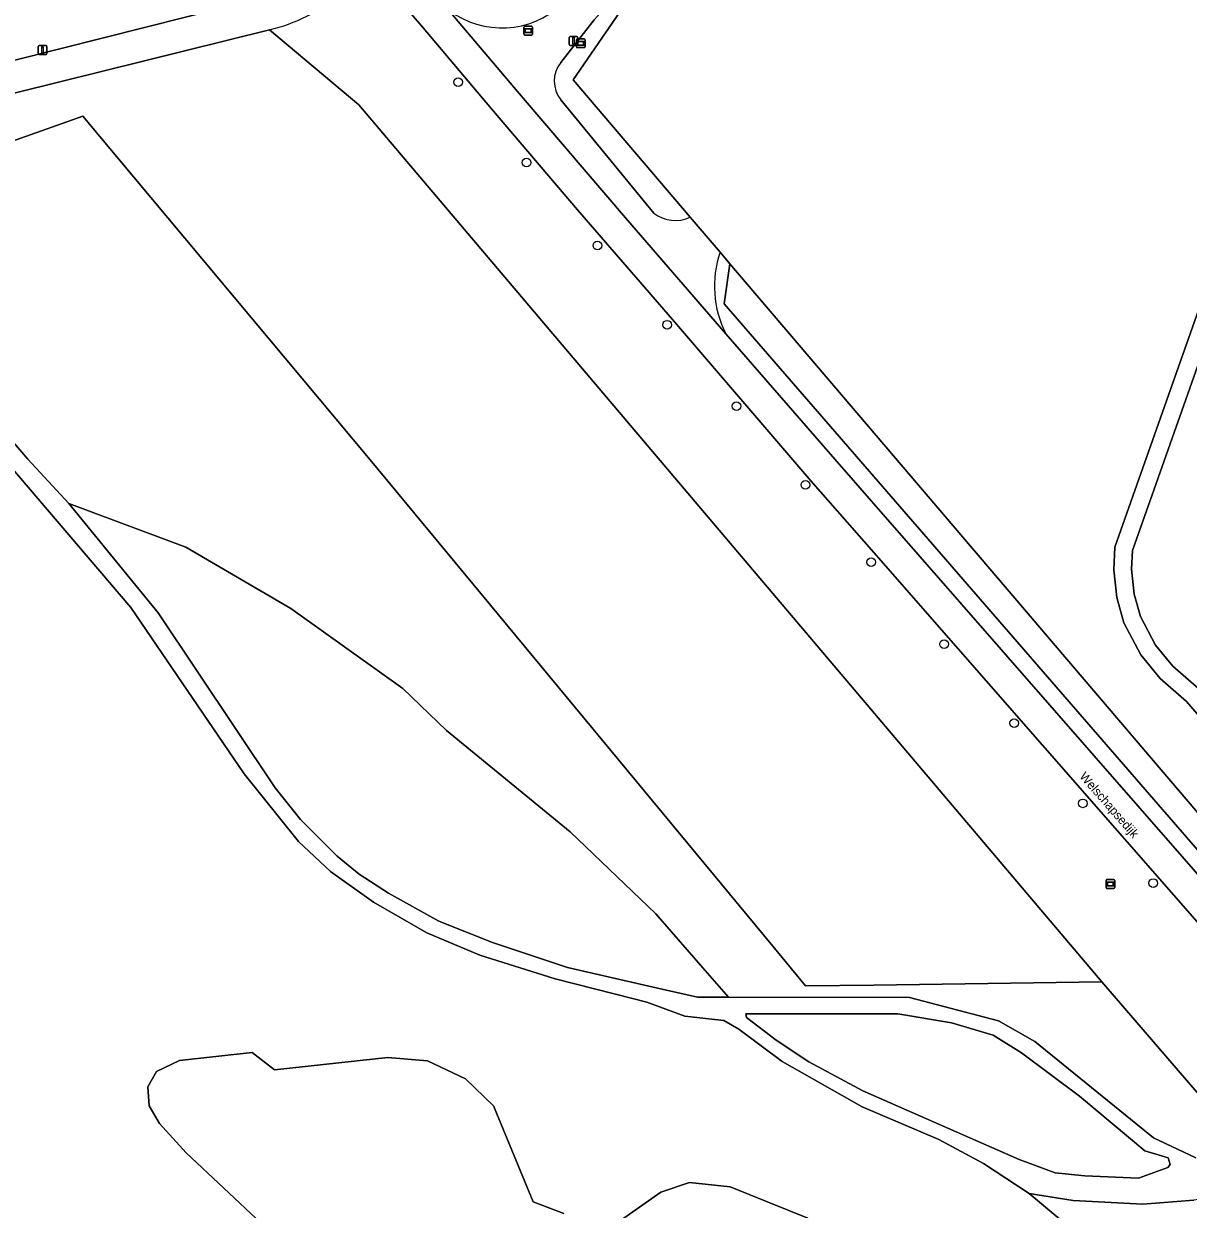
# Model space of a CAD drawing. Extents: x 156061 to 157804, y 383437 to 385640.
# Drawn here: x 156904 to 157035.5, y 384500.7 to 384634.6 of the extents above; entities that cross this region are included whole.
import ezdxf

# ---------------------------------------------------------------- set-up
doc = ezdxf.new("R2010")
doc.units = 0
for name, color, linetype in [('IMGEO_Afsluitpaal', 7, 'Continuous'), ('IMGEO_Berm_groen', 7, 'Continuous'), ('IMGEO_Boom', 7, 'Continuous'), ('IMGEO_Fietspad_gesloten', 7, 'Continuous'), ('IMGEO_Grasland_overig', 7, 'Continuous'), ('IMGEO_Groenvoorziening', 7, 'Continuous'), ('IMGEO_Hek', 7, 'Continuous'), ('IMGEO_Informatiebord', 7, 'Continuous'), ('IMGEO_Lichtmast', 7, 'Continuous'), ('IMGEO_Loofbos', 7, 'Continuous'), ('IMGEO_Openbare_ruimte_label', 7, 'Continuous'), ('IMGEO_Verklikker', 7, 'Continuous')]:
    doc.layers.add(name, color=color, linetype=linetype)

msp = doc.modelspace()

# ---------------------------------------------------------------- linework, layer by layer
at = {"layer": 'IMGEO_Afsluitpaal'}
for p, q in [((156965.58, 384632.24), (156965.58, 384633.04)), ((156965.58, 384633.04), (156965.58, 384632.24)), ((156965.68, 384633.14), (156966.47, 384633.14)), ((156966.47, 384633.14), (156965.68, 384633.14)), ((156966.47, 384632.14), (156965.68, 384632.14)), ((156965.68, 384632.14), (156966.47, 384632.14)), ((156966.57, 384633.04), (156966.57, 384632.24)), ((156966.57, 384632.24), (156966.57, 384633.04))]:
    msp.add_line(p, q, dxfattribs=at)
msp.add_lwpolyline([(156966, 384633.02), (156966.15, 384633.02), (156966.15, 384632.27), (156966, 384632.27), (156966, 384633.02)], dxfattribs=at)
for centre, start, end in [((156965.68, 384633.04), 90, 180), ((156965.68, 384633.04), 90, 180), ((156965.68, 384632.24), 180, 270), ((156965.68, 384632.24), 180, 270), ((156966.47, 384633.04), 0, 90), ((156966.47, 384633.04), 360, 90), ((156966.47, 384632.24), 270, 0), ((156966.47, 384632.24), 270, 0)]:
    msp.add_arc(centre, 0.1, start, end, dxfattribs=at)
at = {"layer": 'IMGEO_Berm_groen'}
for points in [[(157000, 384574.89), (156992.9, 384582.99), (156977.24, 384601.18), (156966.54, 384613.57), (156956.8, 384625), (156948.92, 384634.34), (156945.58, 384638.24)], [(156931.72, 384633.9), (156941.82, 384625.42), (157025.77, 384526.43), (157043.96, 384505.31), (157056.89, 384509.94), (157000, 384574.89)], [(157000, 384583.48), (156983.08, 384602.98), (156983.75, 384607.5), (156982.63, 384608.81)], [(156983.28, 384599.59), (156995.58, 384585.44), (157000, 384580.39), (157044.99, 384528.95)], [(157047.94, 384528.23), (157046.85, 384529.47), (157000, 384583.48)]]:
    msp.add_lwpolyline(points, dxfattribs=at)
for centre, radius, start, end in [((156927.2, 384652.9), 19.53, 283.3871, 309.9373), ((156957.98, 384644.09), 9.97, 233.2442, 312.8511), ((156994.02, 384604.98), 12.02, 161.4536, 206.6743)]:
    msp.add_arc(centre, radius, start, end, dxfattribs=at)
at = {"layer": 'IMGEO_Boom'}
for centre in [(156953.04, 384628), (156960.78, 384618.93), (156968.77, 384609.56), (156976.65, 384600.61), (156984.48, 384591.41), (156992.27, 384582.53), (156999.7, 384573.79), (157007.93, 384564.55), (157015.85, 384555.62), (157023.62, 384546.57), (157031.55, 384537.57)]:
    msp.add_circle(centre, 0.489, dxfattribs=at)
at = {"layer": 'IMGEO_Fietspad_gesloten'}
for points in [[(156934.94, 384639.2), (156931.97, 384637.82), (156888.89, 384626.92), (156886.5, 384626.31), (156885.81, 384626.14)], [(156945.58, 384638.24), (156948.92, 384634.34), (156956.8, 384625), (156966.54, 384613.57), (156977.24, 384601.18), (156992.9, 384582.99), (157000, 384574.89), (157056.89, 384509.94), (157058.63, 384507.87), (157065.54, 384500), (157136.46, 384419.32), (157161.96, 384390.33), (157163.6, 384388.4), (157250.85, 384289.34), (157285.45, 384250), (157313.49, 384218.11)], [(157139.19, 384421.58), (157070.34, 384500), (157064.75, 384506.36), (157062.1, 384509.4), (157060.34, 384511.41), (157052.37, 384520.52), (157044.99, 384528.95), (157000, 384580.39), (156995.58, 384585.44), (156983.28, 384599.59), (156971.95, 384612.68), (156960.39, 384626.17), (156952.01, 384636.1)], [(156886.51, 384622.67), (156886.95, 384622.78), (156888.9, 384623.27), (156931.72, 384633.9)]]:
    msp.add_lwpolyline(points, dxfattribs=at)
msp.add_arc((156927.2, 384652.9), 19.53, 283.3871, 309.9373, dxfattribs=at)
at = {"layer": 'IMGEO_Grasland_overig'}
for points in [[(156964.63, 384630.23), (156968.41, 384635.04), (156970.77, 384637.72), (156972.78, 384640.58), (156980.96, 384652.91), (156993.25, 384670.61)], [(156952.01, 384636.1), (156960.39, 384626.17), (156971.95, 384612.68), (156983.28, 384599.59)], [(156975.15, 384613.22), (156964.64, 384625.99)], [(157040.94, 384614.31), (157027.24, 384575.5), (157027.1, 384572.94), (157027.45, 384569.81), (157028.23, 384566.94), (157030.15, 384563.32), (157032.33, 384560.65), (157035.31, 384558.06), (157042.95, 384549.21)], [(157036.73, 384559.48), (157033.77, 384562.04), (157031.82, 384564.43), (157030.11, 384567.68), (157029.42, 384570.18), (157029.11, 384573), (157029.23, 384575.1), (157042.84, 384613.69)], [(156982.63, 384608.81), (156979.27, 384612.75)], [(157036.38, 384506.54), (157031.6, 384508.79), (157018.2, 384519.68), (157014.07, 384522.01), (157004.02, 384524.63), (156983.59, 384524.68), (156980.07, 384524.69), (156975.43, 384525.74), (156965.39, 384528.02), (156956.92, 384530.86), (156950.86, 384533.28), (156945.16, 384536.42), (156941.85, 384538.59), (156939.37, 384540.6), (156935.23, 384544.74), (156932.38, 384548.32), (156919.14, 384568.06), (156909.06, 384580.42), (156904.43, 384585.42), (156896.64, 384594.46)], [(156900.93, 384586.38), (156916.07, 384568.69), (156928.86, 384549.9), (156935, 384542.26), (156938.61, 384538.86), (156943.48, 384535.42), (156949.52, 384531.94), (156955.48, 384529.42), (156964.01, 384526.75), (156972.89, 384524.49), (156974.36, 384524.11), (156978.64, 384522.54), (156983.06, 384522.07), (156984.77, 384521.07), (156989.64, 384517.42), (156998.67, 384512.3), (157007.35, 384508.6), (157012.39, 384505.9), (157017.56, 384502.51), (157022.53, 384501.72), (157030.4, 384501.33), (157036.14, 384501.76)]]:
    msp.add_lwpolyline(points, dxfattribs=at)
msp.add_lwpolyline([(156985.54, 384522.81), (157002.71, 384522.81), (157008.76, 384521.77), (157013.5, 384520.38), (157016.7, 384518.42), (157023.25, 384513.52), (157030.63, 384507.32), (157033.25, 384506.55), (157033.47, 384505.8), (157033.22, 384505.45), (157029.91, 384504.26), (157023.82, 384504.52), (157020.48, 384504.87), (157016.4, 384506.34), (156998.77, 384514.12), (156992.67, 384517.4), (156988.97, 384519.83), (156985.6, 384522.4)], close=True, dxfattribs=at)
for centre, radius, start, end in [((156957.98, 384644.09), 9.97, 233.2442, 312.8511), ((156967.29, 384628.11), 3.39, 141.4401, 218.776), ((156977.6, 384616.38), 4, 232.2364, 294.7106), ((156994.02, 384604.98), 12.02, 161.4536, 206.6743)]:
    msp.add_arc(centre, radius, start, end, dxfattribs=at)
at = {"layer": 'IMGEO_Groenvoorziening'}
for points in [[(156966.05, 384628.27), (157109.09, 384836.1)], [(157109.09, 384836.1), (156966.05, 384628.27), (156979.27, 384612.75), (156982.63, 384608.81), (156983.75, 384607.5), (157050.93, 384528.66), (157054.27, 384530.42), (157042.95, 384549.21), (157035.31, 384558.06), (157032.33, 384560.65), (157030.15, 384563.32), (157028.23, 384566.94), (157027.45, 384569.81), (157027.1, 384572.94), (157027.24, 384575.5), (157040.94, 384614.31), (157042, 384617.87), (157042.68, 384620.88), (157043.08, 384626.8), (157043.26, 384633.37), (157043.53, 384637.35)], [(156993.25, 384670.61), (156980.96, 384652.91), (156972.78, 384640.58), (156970.77, 384637.72), (156968.41, 384635.04), (156964.63, 384630.23)], [(157045.52, 384637.12), (157045.25, 384633.28), (157045.08, 384626.7), (157044.66, 384620.59), (157043.94, 384617.36), (157042.84, 384613.69), (157029.23, 384575.1), (157029.11, 384573), (157029.42, 384570.18), (157030.11, 384567.68), (157031.82, 384564.43), (157033.77, 384562.04), (157036.73, 384559.48), (157044.57, 384550.39), (157055.48, 384532.29), (157057.21, 384532.07), (157101.92, 384556.39), (157234.91, 384629.94), (157303.66, 384667.61)], [(156979.27, 384612.75), (156966.05, 384628.27)], [(156964.64, 384625.99), (156975.15, 384613.22)], [(157043.96, 384505.31), (157025.77, 384526.43), (157000, 384526.06), (156992.3, 384525.98), (156988.59, 384530.46), (156943.1, 384585.36), (156910.63, 384624.14), (156888.96, 384616.46)], [(157050.93, 384528.66), (156983.75, 384607.5), (156983.08, 384602.98), (157000, 384583.48), (157046.85, 384529.47), (157047.94, 384528.23)], [(156896.64, 384594.46), (156904.43, 384585.42), (156909.06, 384580.42), (156922.3, 384575.48), (156934.15, 384568.55), (156946.78, 384559.52), (156951.73, 384554.8), (156965.69, 384543.36), (156975.38, 384534.08), (156980.68, 384528.01), (156983.59, 384524.68), (157004.02, 384524.63), (157014.07, 384522.01), (157018.2, 384519.68), (157031.6, 384508.79), (157036.38, 384506.54)], [(157027.06, 384494.56), (157017.56, 384502.51), (157012.39, 384505.9), (157007.35, 384508.6), (156998.67, 384512.3), (156989.64, 384517.42), (156984.77, 384521.07), (156983.06, 384522.07), (156978.64, 384522.54), (156974.36, 384524.11), (156972.89, 384524.49), (156964.01, 384526.75), (156955.48, 384529.42), (156949.52, 384531.94), (156943.48, 384535.42), (156938.61, 384538.86), (156935, 384542.26), (156928.86, 384549.9), (156916.07, 384568.69), (156900.93, 384586.38)], [(156943.61, 384487.16), (156922.33, 384507.12), (156919.29, 384510.43), (156918.15, 384512.43), (156917.98, 384514.56), (156918.98, 384516.3), (156921.56, 384517.53), (156929.77, 384518.45), (156932.3, 384516.49), (156945.09, 384517.86), (156949.58, 384517.48), (156953.86, 384515.46), (156957.08, 384512.38), (156957.16, 384512.17), (156961.51, 384501.59), (156965, 384500.26)], [(156965, 384500.26), (156961.51, 384501.59), (156957.16, 384512.17), (156957.08, 384512.38), (156953.86, 384515.46), (156949.58, 384517.48), (156945.09, 384517.86), (156932.3, 384516.49), (156929.77, 384518.45), (156921.56, 384517.53), (156918.98, 384516.3), (156917.98, 384514.56), (156918.15, 384512.43), (156919.29, 384510.43), (156922.33, 384507.12), (156943.61, 384487.16)], [(156971.39, 384499.48), (156975.95, 384502.66), (156979.17, 384503.78), (156983.78, 384503.26), (156992.55, 384499.73)], [(156992.55, 384499.73), (156983.78, 384503.26), (156979.17, 384503.78), (156975.95, 384502.66), (156971.39, 384499.48)], [(157048.52, 384500), (157045.77, 384503.22), (157045.66, 384503.18), (157041.77, 384502.51), (157036.14, 384501.76), (157030.4, 384501.33), (157022.53, 384501.72), (157017.56, 384502.51), (157027.06, 384494.56)]]:
    msp.add_lwpolyline(points, dxfattribs=at)
for points in [[(156980.68, 384528.01), (156975.38, 384534.08), (156965.69, 384543.36), (156951.73, 384554.8), (156946.78, 384559.52), (156934.15, 384568.55), (156922.3, 384575.48), (156909.06, 384580.42), (156919.14, 384568.06), (156932.38, 384548.32), (156935.23, 384544.74), (156939.37, 384540.6), (156941.85, 384538.59), (156945.16, 384536.42), (156950.86, 384533.28), (156956.92, 384530.86), (156965.39, 384528.02), (156975.43, 384525.74), (156980.07, 384524.69), (156983.59, 384524.68)], [(156985.6, 384522.4), (156988.97, 384519.83), (156992.67, 384517.4), (156998.77, 384514.12), (157016.4, 384506.34), (157020.48, 384504.87), (157023.82, 384504.52), (157029.91, 384504.26), (157033.22, 384505.45), (157033.47, 384505.8), (157033.25, 384506.55), (157030.63, 384507.32), (157023.25, 384513.52), (157016.7, 384518.42), (157013.5, 384520.38), (157008.76, 384521.77), (157002.71, 384522.81), (156985.54, 384522.81)]]:
    msp.add_lwpolyline(points, close=True, dxfattribs=at)
for centre, radius, start, end in [((156967.29, 384628.11), 3.39, 141.4401, 218.776), ((156977.6, 384616.38), 4, 232.2364, 294.7106)]:
    msp.add_arc(centre, radius, start, end, dxfattribs=at)
at = {"layer": 'IMGEO_Hek'}
for points in [[(156979.27, 384612.75), (156966.05, 384628.27), (157109.09, 384836.1)], [(156931.72, 384633.9), (156941.82, 384625.42)], [(157025.77, 384526.43), (156941.82, 384625.42)], [(156982.63, 384608.81), (156979.27, 384612.75)], [(156983.75, 384607.5), (156982.63, 384608.81)], [(157050.93, 384528.66), (156983.75, 384607.5)]]:
    msp.add_lwpolyline(points, dxfattribs=at)
at = {"layer": 'IMGEO_Informatiebord'}
for p, q in [((156960.46, 384633.41), (156960.46, 384634.21)), ((156960.46, 384634.21), (156960.46, 384633.41)), ((156960.56, 384634.31), (156961.35, 384634.31)), ((156961.35, 384634.31), (156960.56, 384634.31)), ((156961.35, 384633.31), (156960.56, 384633.31)), ((156960.56, 384633.31), (156961.35, 384633.31)), ((156961.45, 384634.21), (156961.45, 384633.41)), ((156961.45, 384633.41), (156961.45, 384634.21)), ((156966.4, 384631.99), (156966.4, 384632.79)), ((156966.4, 384632.79), (156966.4, 384631.99)), ((156966.5, 384632.89), (156967.28, 384632.89)), ((156967.28, 384632.89), (156966.5, 384632.89)), ((156967.28, 384631.89), (156966.5, 384631.89)), ((156966.5, 384631.89), (156967.28, 384631.89)), ((156967.38, 384632.79), (156967.38, 384631.99)), ((156967.38, 384631.99), (156967.38, 384632.79))]:
    msp.add_line(p, q, dxfattribs=at)
for points in [[(156960.56, 384634.04), (156961.34, 384634.04), (156961.34, 384633.58), (156960.56, 384633.58), (156960.56, 384634.04)], [(156960.62, 384633.98), (156960.62, 384633.64), (156961.28, 384633.64), (156961.28, 384633.98), (156960.62, 384633.98)], [(156966.5, 384632.62), (156967.28, 384632.62), (156967.28, 384632.15), (156966.5, 384632.15), (156966.5, 384632.62)], [(156966.56, 384632.55), (156966.56, 384632.22), (156967.22, 384632.22), (156967.22, 384632.55), (156966.56, 384632.55)]]:
    msp.add_lwpolyline(points, dxfattribs=at)
for centre, start, end in [((156960.56, 384634.21), 90, 180), ((156960.56, 384634.21), 90, 180), ((156960.56, 384633.41), 180, 270), ((156960.56, 384633.41), 180, 270), ((156961.35, 384634.21), 0, 90), ((156961.35, 384634.21), 360, 90), ((156961.35, 384633.41), 270, 0), ((156961.35, 384633.41), 270, 0), ((156966.5, 384632.79), 90, 180), ((156966.5, 384632.79), 90, 180), ((156966.5, 384631.99), 180, 270), ((156966.5, 384631.99), 180, 270), ((156967.28, 384632.79), 0, 90), ((156967.28, 384632.79), 360, 90), ((156967.28, 384631.99), 270, 0), ((156967.28, 384631.99), 270, 0)]:
    msp.add_arc(centre, 0.1, start, end, dxfattribs=at)
at = {"layer": 'IMGEO_Lichtmast'}
for p, q in [((156905.61, 384631.22), (156905.61, 384632.02)), ((156905.61, 384632.02), (156905.61, 384631.22)), ((156905.71, 384632.12), (156906.5, 384632.12)), ((156906.5, 384632.12), (156905.71, 384632.12)), ((156906.6, 384632.02), (156906.6, 384631.22)), ((156906.6, 384631.22), (156906.6, 384632.02)), ((156906.5, 384631.12), (156905.71, 384631.12)), ((156905.71, 384631.12), (156906.5, 384631.12))]:
    msp.add_line(p, q, dxfattribs=at)
msp.add_lwpolyline([(156906.03, 384632), (156906.18, 384632), (156906.18, 384631.25), (156906.03, 384631.25), (156906.03, 384632)], dxfattribs=at)
for centre, start, end in [((156905.71, 384632.02), 90, 180), ((156905.71, 384632.02), 90, 180), ((156906.5, 384632.02), 0, 90), ((156906.5, 384632.02), 360, 90), ((156905.71, 384631.22), 180, 270), ((156905.71, 384631.22), 180, 270), ((156906.5, 384631.22), 270, 0), ((156906.5, 384631.22), 270, 0)]:
    msp.add_arc(centre, 0.1, start, end, dxfattribs=at)
at = {"layer": 'IMGEO_Loofbos'}
msp.add_lwpolyline([(156937.33, 384640.75), (156906.38, 384677.17), (156900.59, 384672.36), (156921.96, 384646.24), (156887.64, 384634.58), (156888.89, 384626.92), (156931.97, 384637.82), (156934.94, 384639.2)], dxfattribs=at)
msp.add_lwpolyline([(156931.72, 384633.9), (156888.9, 384623.27), (156888.82, 384620.45), (156888.96, 384616.46), (156910.63, 384624.14), (156943.1, 384585.36), (156988.59, 384530.46), (156992.3, 384525.98), (157000, 384526.06), (157025.77, 384526.43), (156941.82, 384625.42)], close=True, dxfattribs=at)
at = {"layer": 'IMGEO_Verklikker'}
for p, q in [((157026.23, 384537.06), (157026.23, 384537.86)), ((157026.23, 384537.86), (157026.23, 384537.06)), ((157026.33, 384537.96), (157027.11, 384537.96)), ((157027.11, 384537.96), (157026.33, 384537.96)), ((157027.11, 384536.96), (157026.33, 384536.96)), ((157026.33, 384536.96), (157027.11, 384536.96)), ((157027.21, 384537.86), (157027.21, 384537.06)), ((157027.21, 384537.06), (157027.21, 384537.86))]:
    msp.add_line(p, q, dxfattribs=at)
for points in [[(157026.33, 384537.7), (157027.11, 384537.7), (157027.11, 384537.23), (157026.33, 384537.23), (157026.33, 384537.7)], [(157026.39, 384537.63), (157026.39, 384537.3), (157027.05, 384537.3), (157027.05, 384537.63), (157026.39, 384537.63)]]:
    msp.add_lwpolyline(points, dxfattribs=at)
for centre, start, end in [((157026.33, 384537.86), 90, 180), ((157026.33, 384537.86), 90, 180), ((157026.33, 384537.06), 180, 270), ((157026.33, 384537.06), 180, 270), ((157027.11, 384537.86), 0, 90), ((157027.11, 384537.86), 360, 90), ((157027.11, 384537.06), 270, 0), ((157027.11, 384537.06), 270, 0)]:
    msp.add_arc(centre, 0.1, start, end, dxfattribs=at)

# ---------------------------------------------------------------- texts
at = {"layer": 'IMGEO_Openbare_ruimte_label'}
msp.add_text('Welschapsedijk', height=1, rotation=311.1482, dxfattribs=at).set_placement((157023.17, 384549.56))

doc.saveas('drawing.dxf')
